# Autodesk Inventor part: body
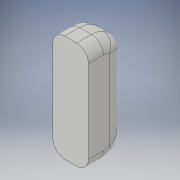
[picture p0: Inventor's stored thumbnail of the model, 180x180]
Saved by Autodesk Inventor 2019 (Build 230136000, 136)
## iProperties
Created: 2020-08
Part Number: body
Material: 一般
Document SubType Name: Modeling
Designer: kikut
Density: 1 g/cm^3
Appearance: 既定
Author: kikut
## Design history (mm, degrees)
sketch "スケッチ1"
  geometry: L1 (-0.06, -0.18)-(0.06, -0.18); L2 (0.06, -0.18)-(0.06, 0.18); L3 (0.06, 0.18)-(-0.06, 0.18); L4 (-0.06, 0.18)-(-0.06, -0.18); L5 (-0.06, -0.18)-(0.06, 0.18); L6 (0.06, -0.18)-(-0.06, 0.18); 1 further point
  constraints: 12 end point, 2 midpoint, 2 parallel, 1 horizontal, 1 perpendicular
  dimensions: "d0" = 0.36 distance of L1.end L2.end; "d1" = 0.12 distance of L2.end L3.end
extrude "押し出し1" new body sketch "スケッチ1" distance "d2" = 0.06; taper "d4" = 0 deg; dims "d3" = 0.07, "d5" = 0
fillet "フィレット2" dims "d7" = 0.08
sketch "スケッチ2"
  geometry: L1 (0.12, -0.05)-(0.12, -0.13) reference; L2 (0.12, -0.07)-(0.14, -0.07); L3 (0.14, -0.07)-(0.14, -0.17); L4 (0.14, -0.17)-(-0.02, -0.17); L5 (-0.02, -0.17)-(-0.02, -0.07); L6 (-0.02, -0.07)-(0, -0.07); L7 (0, 0)-(0.12, 0) reference; A1 r 0.06 centre (0.06, -0.07) between (0, -0.07) and (0.12, -0.07); 1 further point
  constraints: 10 end point, 4 perpendicular, 2 point on circle, 2 point on line, 1 centre point, 1 horizontal
  dimensions: "d8" = 0.06 radius of A1; "d9" = 0.02 distance of L5.end L6.end; "d10" = 0.02 distance of L2.start L2.end; "d11" = 0.16 distance of L3.end L4.end; "d12" = 0.1 distance of L2.end L3.end; "d13" = 0.13 dimension on A1 L7
extrude "押し出し2" cut sketch "スケッチ2" extent not by distance; stored distance "d14" = 0.06; taper "d15" = 0 deg
fillet "フィレット3" dims "d16" = 0.04
node "ソリッド1"
